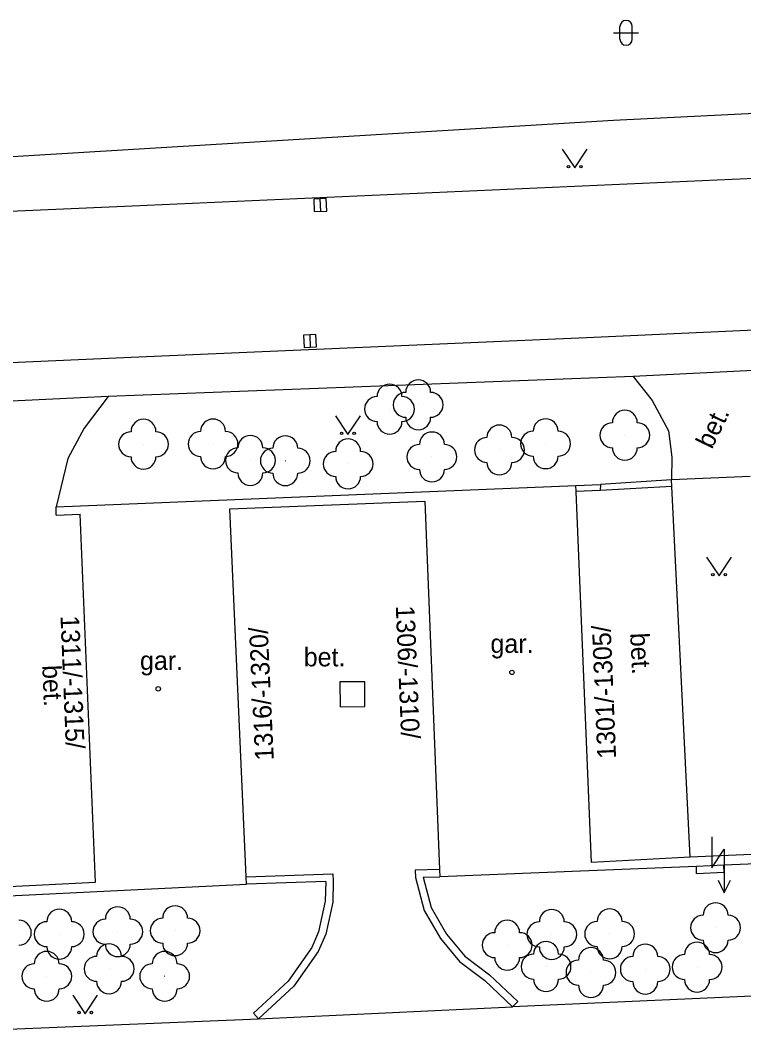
# Model space of a CAD drawing. Extents: x -737812 to -729375, y -1123000 to -1115500.
# Drawn here: x -736474.12 to -736445.1, y -1118221.56 to -1118180.76 of the extents above; entities that cross this region are included whole.
import ezdxf

# ---------------------------------------------------------------- set-up
doc = ezdxf.new("R2010")
doc.units = 0
for name, color, linetype in [('Doplněk polohopisu', 7, 'Continuous'), ('Hranice - ploty_ zdi', 7, 'Continuous'), ('Komunikace', 7, 'Continuous'), ('Pomocné popisy', 7, 'Continuous'), ('Popisy budov', 7, 'Continuous'), ('Povr_ zn_ inž_ sítí - el_', 7, 'Continuous'), ('Povr_ zn_ inž_ sítí - kan_', 7, 'Continuous'), ('Povr_ zn_ inž_ sítí - ner_', 7, 'Continuous'), ('Stavební objekty', 7, 'Continuous'), ('Zeleň', 7, 'Continuous'), ('Značky druhů budov', 7, 'Continuous'), ('Značky druhů pozemků', 7, 'Continuous'), ('Čísla popisná', 7, 'Continuous')]:
    doc.layers.add(name, color=color, linetype=linetype)

msp = doc.modelspace()

# ---------------------------------------------------------------- linework, layer by layer
at = {"layer": 'Doplněk polohopisu'}
msp.add_line((-736449.54, -1118195.04), (-736470.6, -1118195.85), dxfattribs=at)
for points in [[(-736449.54, -1118195.04), (-736448.78, -1118196)], [(-736470.6, -1118195.85), (-736471.56, -1118197.11)], [(-736448.78, -1118196), (-736448.12, -1118197.22)], [(-736471.56, -1118197.11), (-736472.21, -1118198.33)], [(-736448.12, -1118197.22), (-736447.99, -1118198.28)], [(-736472.21, -1118198.33), (-736472.68, -1118200.27)], [(-736447.99, -1118198.28), (-736448, -1118199.19)], [(-736444.84, -1118199.05), (-736448, -1118199.19)], [(-736447.25, -1118214.32), (-736447.99, -1118199.45)]]:
    msp.add_lwpolyline(points, dxfattribs=at)
at = {"layer": 'Hranice - ploty_ zdi'}
for points in [[(-736447.99, -1118199.45), (-736450.86, -1118199.62)], [(-736448, -1118199.19), (-736450.85, -1118199.37)], [(-736447.99, -1118199.45), (-736448, -1118199.19)], [(-736457.3, -1118214.81), (-736458.28, -1118214.84)], [(-736458.28, -1118214.84), (-736458.27, -1118215.14)], [(-736465.06, -1118215.11), (-736461.58, -1118214.99)], [(-736461.87, -1118215.3), (-736465.05, -1118215.41)], [(-736461.87, -1118215.3), (-736461.89, -1118216.09)], [(-736461.57, -1118215.29), (-736461.59, -1118216.13)], [(-736461.58, -1118214.99), (-736461.57, -1118215.29)], [(-736458.27, -1118215.14), (-736457.92, -1118216.46)], [(-736457.96, -1118215.13), (-736457.29, -1118215.11)], [(-736457.96, -1118215.13), (-736457.64, -1118216.34)], [(-736461.89, -1118216.09), (-736462.16, -1118217.32)], [(-736461.59, -1118216.13), (-736461.87, -1118217.41)], [(-736457.92, -1118216.46), (-736457.27, -1118217.58)], [(-736457.64, -1118216.34), (-736457.02, -1118217.41)], [(-736462.16, -1118217.32), (-736462.43, -1118217.95)], [(-736461.87, -1118217.41), (-736462.17, -1118218.1)], [(-736457.02, -1118217.41), (-736456.29, -1118218.29)], [(-736457.27, -1118217.58), (-736456.5, -1118218.51)], [(-736462.43, -1118217.95), (-736463.38, -1118219.29)], [(-736462.17, -1118218.1), (-736463.15, -1118219.49)], [(-736456.5, -1118218.51), (-736455.49, -1118219.27)], [(-736456.29, -1118218.29), (-736455.3, -1118219.04)], [(-736455.3, -1118219.04), (-736454.16, -1118220.11)], [(-736463.38, -1118219.29), (-736464.77, -1118220.58)], [(-736455.49, -1118219.27), (-736454.37, -1118220.33)], [(-736463.15, -1118219.49), (-736464.57, -1118220.8)], [(-736454.37, -1118220.33), (-736454.16, -1118220.11)], [(-736464.57, -1118220.8), (-736464.77, -1118220.58)]]:
    msp.add_lwpolyline(points, dxfattribs=at)
at = {"layer": 'Komunikace'}
for p, q in [((-736443.01, -1118194.72), (-736449.54, -1118195.04)), ((-736470.6, -1118195.85), (-736478.12, -1118196.2))]:
    msp.add_line(p, q, dxfattribs=at)
for points in [[(-736382.94, -1118184.33), (-736394.28, -1118184.84), (-736415.42, -1118185.79), (-736441.35, -1118186.96), (-736469.63, -1118188.21), (-736497.82, -1118189.44), (-736525.6, -1118190.68), (-736553.59, -1118191.9), (-736582.16, -1118193.13)], [(-736581.67, -1118199.22), (-736563.35, -1118198.45), (-736553.37, -1118198), (-736535.19, -1118197.19), (-736525.2, -1118196.72), (-736507.22, -1118195.93), (-736497.34, -1118195.5), (-736479.37, -1118194.7), (-736469.37, -1118194.25), (-736451.41, -1118193.48), (-736441.43, -1118193.02), (-736418.32, -1118192.01), (-736415.33, -1118192.1), (-736413.62, -1118192.35), (-736411.05, -1118193)], [(-736436.35, -1118219.52), (-736454.37, -1118220.33)], [(-736464.57, -1118220.8), (-736454.37, -1118220.33)], [(-736482.67, -1118221.56), (-736464.57, -1118220.8)]]:
    msp.add_lwpolyline(points, dxfattribs=at)
at = {"layer": 'Povr_ zn_ inž_ sítí - el_'}
for points in [[(-736446.38, -1118213.5), (-736446.38, -1118214.75), (-736445.88, -1118214), (-736445.88, -1118215.75)], [(-736446.13, -1118215.25), (-736445.88, -1118215.75), (-736445.63, -1118215.25)]]:
    msp.add_lwpolyline(points, dxfattribs=at)
at = {"layer": 'Povr_ zn_ inž_ sítí - kan_'}
for p, q in [((-736462.101, -1118187.92), (-736462.079, -1118188.42)), ((-736462.511, -1118193.37), (-736462.489, -1118193.87))]:
    msp.add_line(p, q, dxfattribs=at)
for points in [[(-736462.352, -1118187.931), (-736462.33, -1118188.431), (-736461.829, -1118188.409), (-736461.851, -1118187.909)], [(-736462.761, -1118193.381), (-736462.74, -1118193.881), (-736462.239, -1118193.86), (-736462.26, -1118193.359)]]:
    msp.add_lwpolyline(points, close=True, dxfattribs=at)
at = {"layer": 'Povr_ zn_ inž_ sítí - ner_'}
for p, q in [((-736460.306, -1118207.284), (-736461.306, -1118207.296)), ((-736461.306, -1118207.296), (-736461.294, -1118208.296)), ((-736460.294, -1118208.284), (-736460.306, -1118207.284)), ((-736461.294, -1118208.296), (-736460.294, -1118208.284))]:
    msp.add_line(p, q, dxfattribs=at)
at = {"layer": 'Stavební objekty'}
for points in [[(-736472.68, -1118200.27), (-736451.83, -1118199.41), (-736450.85, -1118199.37)], [(-736451.21, -1118214.54), (-736451.82, -1118199.66), (-736451.83, -1118199.41)], [(-736450.85, -1118199.37), (-736450.86, -1118199.62)], [(-736450.86, -1118199.62), (-736451.82, -1118199.66)], [(-736472.68, -1118200.61), (-736472.68, -1118200.27)], [(-736465.71, -1118200.35), (-736457.89, -1118200.04)], [(-736457.89, -1118200.04), (-736457.3, -1118214.81), (-736457.29, -1118215.11)], [(-736472.68, -1118200.61), (-736471.72, -1118200.57)], [(-736471.11, -1118215.32), (-736471.72, -1118200.57)], [(-736465.05, -1118215.41), (-736465.06, -1118215.11), (-736465.71, -1118200.35)], [(-736443.25, -1118214.15), (-736447.25, -1118214.32)], [(-736437.14, -1118214.28), (-736445.9, -1118214.64), (-736447, -1118214.69), (-736457.29, -1118215.11)], [(-736447.25, -1118214.32), (-736451.21, -1118214.54)], [(-736446.99, -1118214.97), (-736447, -1118214.69)], [(-736446.99, -1118214.97), (-736445.89, -1118214.92)], [(-736445.89, -1118214.92), (-736445.9, -1118214.64)], [(-736474.84, -1118215.51), (-736471.11, -1118215.32)], [(-736485.09, -1118216.4), (-736475.96, -1118215.95), (-736474.86, -1118215.89), (-736465.05, -1118215.41)]]:
    msp.add_lwpolyline(points, dxfattribs=at)
at = {"layer": 'Zeleň'}
for points in [[(-736450.32, -1118184.77), (-736423.07, -1118183.41)], [(-736475.35, -1118186.27), (-736450.32, -1118184.77)]]:
    msp.add_lwpolyline(points, dxfattribs=at)
for centre in [(-736458.16, -1118196.18), (-736459.31, -1118196.35), (-736449.87, -1118197.4), (-736469.18, -1118197.76), (-736466.39, -1118197.75), (-736453.05, -1118197.74), (-736454.9, -1118197.99), (-736464.89, -1118198.41), (-736463.49, -1118198.42), (-736460.97, -1118198.55), (-736457.61, -1118198.27), (-736472.56, -1118217.41), (-736470.21, -1118217.31), (-736467.91, -1118217.27), (-736452.8, -1118217.42), (-736450.48, -1118217.4), (-736446.23, -1118217.15), (-736454.59, -1118217.85), (-736470.56, -1118218.8), (-736453.03, -1118218.71), (-736451.23, -1118218.95), (-736449.05, -1118218.81), (-736446.97, -1118218.73), (-736473.06, -1118219.1), (-736468.33, -1118219.1)]:
    msp.add_circle(centre, 0.0005, dxfattribs=at)
for centre, start, end in [((-736459.31, -1118195.85), 360, 180), ((-736458.16, -1118195.68), 360, 180), ((-736458.66, -1118196.18), 90, 270), ((-736457.66, -1118196.18), 270, 90), ((-736459.81, -1118196.35), 90, 270), ((-736458.81, -1118196.35), 270, 90), ((-736449.87, -1118196.9), 360, 180), ((-736469.18, -1118197.26), 360, 180), ((-736466.39, -1118197.25), 360, 180), ((-736459.31, -1118196.85), 180, 360), ((-736458.16, -1118196.68), 180, 360), ((-736454.9, -1118197.49), 360, 180), ((-736453.05, -1118197.24), 360, 180), ((-736450.37, -1118197.4), 90, 270), ((-736449.37, -1118197.4), 270, 90), ((-736469.68, -1118197.76), 90, 270), ((-736468.68, -1118197.76), 270, 90), ((-736466.89, -1118197.75), 90, 270), ((-736465.89, -1118197.75), 270, 90), ((-736464.89, -1118197.91), 360, 180), ((-736463.49, -1118197.92), 360, 180), ((-736457.61, -1118197.77), 360, 180), ((-736453.55, -1118197.74), 90, 270), ((-736452.55, -1118197.74), 270, 90), ((-736460.97, -1118198.05), 360, 180), ((-736458.11, -1118198.27), 90, 270), ((-736457.11, -1118198.27), 270, 90), ((-736455.4, -1118197.99), 90, 270), ((-736454.4, -1118197.99), 270, 90), ((-736466.39, -1118198.25), 180, 360), ((-736465.39, -1118198.41), 90, 270), ((-736463.99, -1118198.42), 90, 270), ((-736464.39, -1118198.41), 270, 90), ((-736462.99, -1118198.42), 270, 90), ((-736461.47, -1118198.55), 90, 270), ((-736460.47, -1118198.55), 270, 90), ((-736453.05, -1118198.24), 180, 360), ((-736449.87, -1118197.9), 180, 360), ((-736469.18, -1118198.26), 180, 360), ((-736454.9, -1118198.49), 180, 360), ((-736464.89, -1118198.91), 180, 360), ((-736463.49, -1118198.92), 180, 360), ((-736460.97, -1118199.05), 180, 360), ((-736457.61, -1118198.77), 180, 360), ((-736446.23, -1118216.65), 360, 180), ((-736472.56, -1118216.91), 360, 180), ((-736470.21, -1118216.81), 360, 180), ((-736467.91, -1118216.77), 360, 180), ((-736452.8, -1118216.92), 360, 180), ((-736450.48, -1118216.9), 360, 180), ((-736474.18, -1118217.35), 270, 90), ((-736473.06, -1118217.41), 90, 270), ((-736472.06, -1118217.41), 270, 90), ((-736470.71, -1118217.31), 90, 270), ((-736469.71, -1118217.31), 270, 90), ((-736468.41, -1118217.27), 90, 270), ((-736467.41, -1118217.27), 270, 90), ((-736454.59, -1118217.35), 360, 180), ((-736453.3, -1118217.42), 90, 270), ((-736452.3, -1118217.42), 270, 90), ((-736450.98, -1118217.4), 90, 270), ((-736449.98, -1118217.4), 270, 90), ((-736446.73, -1118217.15), 90, 270), ((-736445.73, -1118217.15), 270, 90), ((-736455.09, -1118217.85), 90, 270), ((-736454.09, -1118217.85), 270, 90), ((-736470.56, -1118218.3), 360, 180), ((-736470.21, -1118217.81), 180, 360), ((-736467.91, -1118217.77), 180, 360), ((-736453.03, -1118218.21), 360, 180), ((-736449.05, -1118218.31), 360, 180), ((-736446.97, -1118218.23), 360, 180), ((-736446.23, -1118217.65), 180, 360), ((-736473.06, -1118218.6), 360, 180), ((-736472.56, -1118217.91), 180, 360), ((-736468.33, -1118218.6), 360, 180), ((-736453.53, -1118218.71), 90, 270), ((-736452.8, -1118217.92), 180, 360), ((-736452.53, -1118218.71), 270, 90), ((-736451.23, -1118218.45), 360, 180), ((-736450.48, -1118217.9), 180, 360), ((-736447.47, -1118218.73), 90, 270), ((-736446.47, -1118218.73), 270, 90), ((-736473.56, -1118219.1), 90, 270), ((-736472.56, -1118219.1), 270, 90), ((-736471.06, -1118218.8), 90, 270), ((-736470.06, -1118218.8), 270, 90), ((-736468.83, -1118219.1), 90, 270), ((-736467.83, -1118219.1), 270, 90), ((-736454.59, -1118218.35), 180, 360), ((-736451.73, -1118218.95), 90, 270), ((-736450.73, -1118218.95), 270, 90), ((-736449.55, -1118218.81), 90, 270), ((-736448.55, -1118218.81), 270, 90), ((-736470.56, -1118219.3), 180, 360), ((-736453.03, -1118219.21), 180, 360), ((-736451.23, -1118219.45), 180, 360), ((-736449.05, -1118219.31), 180, 360), ((-736446.97, -1118219.23), 180, 360), ((-736473.06, -1118219.6), 180, 360), ((-736468.33, -1118219.6), 180, 360)]:
    msp.add_arc(centre, 0.5, start, end, dxfattribs=at)
at = {"layer": 'Značky druhů budov'}
for centre in [(-736454.4, -1118206.91), (-736468.59, -1118207.57)]:
    msp.add_circle(centre, 0.0875, dxfattribs=at)
at = {"layer": 'Značky druhů pozemků'}
for p, q in [((-736450.07, -1118181.51), (-736450.07, -1118181.01)), ((-736449.57, -1118181.51), (-736449.57, -1118181.01)), ((-736450.32, -1118181.26), (-736449.32, -1118181.26))]:
    msp.add_line(p, q, dxfattribs=at)
for points in [[(-736452.38, -1118185.93), (-736451.88, -1118186.68), (-736451.38, -1118185.93)], [(-736461.48, -1118196.62), (-736460.98, -1118197.37), (-736460.48, -1118196.62)], [(-736446.59, -1118202.29), (-736446.09, -1118203.04), (-736445.59, -1118202.29)], [(-736472.02, -1118219.85), (-736471.52, -1118220.6), (-736471.02, -1118219.85)]]:
    msp.add_lwpolyline(points, dxfattribs=at)
for centre in [(-736452.13, -1118186.63), (-736451.63, -1118186.63), (-736461.23, -1118197.32), (-736460.73, -1118197.32), (-736446.34, -1118202.99), (-736445.84, -1118202.99), (-736471.77, -1118220.55), (-736471.27, -1118220.55)]:
    msp.add_circle(centre, 0.05, dxfattribs=at)
for centre, start, end in [((-736449.82, -1118181.01), 0, 180), ((-736449.82, -1118181.51), 180, 360)]:
    msp.add_arc(centre, 0.25, start, end, dxfattribs=at)

# ---------------------------------------------------------------- texts
at = {"layer": 'Pomocné popisy'}
for rotation, p in [(63.9789, (-736446.38, -1118197.99)), (272.849, (-736449.66, -1118205.34)), (272.3608, (-736473.24, -1118206.63))]:
    msp.add_text('bet.', height=0.75, rotation=rotation, dxfattribs=at).set_placement(p)
msp.add_text('bet.', height=0.75, dxfattribs=at).set_placement((-736462.75, -1118206.67))
at = {"layer": 'Popisy budov'}
for p in [(-736455.26, -1118206.13), (-736469.32, -1118206.81)]:
    msp.add_text('gar.', height=0.75, dxfattribs=at).set_placement(p)
at = {"layer": 'Čísla popisná'}
for s, rotation, p in [('1306/-1310/', 272.3608, (-736459.06, -1118204.24)), ('1311/-1315/', 272.3608, (-736472.51, -1118204.64)), ('1316/-1320/', 92.6708, (-736463.95, -1118210.43)), ('1301/-1305/', 92.3608, (-736450.22, -1118210.36))]:
    msp.add_text(s, height=0.75, rotation=rotation, dxfattribs=at).set_placement(p)

doc.saveas('drawing.dxf')
